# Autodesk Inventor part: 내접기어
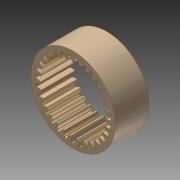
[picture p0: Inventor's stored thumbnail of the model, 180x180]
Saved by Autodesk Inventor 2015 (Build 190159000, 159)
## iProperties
Created: 2023-11
Part Number: 내접기어
Material: 알루미늄 6061
Document SubType Name: Modeling
Designer: mdu-01
Density: 1 g/cm^3
Appearance: 알루미늄 - 평지(1)
Author: mdu-01
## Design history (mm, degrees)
sketch "스케치1" dims "d0" = 75, "d1" = 62, "d3" = 2.5
  geometry: L1 (0, 0)-(0, 37.5); A1 r 29 centre (0, 0) between (0.57, 28.994) and (-0.57, 28.994); A2 r 8.747 centre (-6.664, 33.911) between (0.57, 28.994) and (2.07, 33.436); A3 r 8.747 centre (6.664, 33.911) between (-2.07, 33.436) and (-0.57, 28.994); A4 r 33.5 centre (0, 0) between (2.07, 33.436) and (-2.07, 33.436); 3 further points
  constraints: 9 point on circle, 4 centre point, 3 coincident, 3 symmetric about line, 2 end point, 1 vertical, 1 vertical alignment, 9 other
  dimensions: "d2" = 2 dimension on A1; "d4" = 1.57 distance from line of point (1.57, 30.96) L1; "d5" = 1 horizontal distance of A1.start point (1.57, 30.96); "d6" = 0.5 horizontal distance of A2.end point (1.57, 30.96)
extrude "돌출1" new body sketch "스케치1" distance "d7" = 30; taper "d8" = 0 deg
extrude "돌출2" join sketch "스케치1" distance "d9" = 30; taper "d10" = 0 deg
fillet "모깎기1" dims "d11" = 0.25
node "솔리드1"
pattern_circular "원형 패턴1" dims angle "d13" = 360 deg
